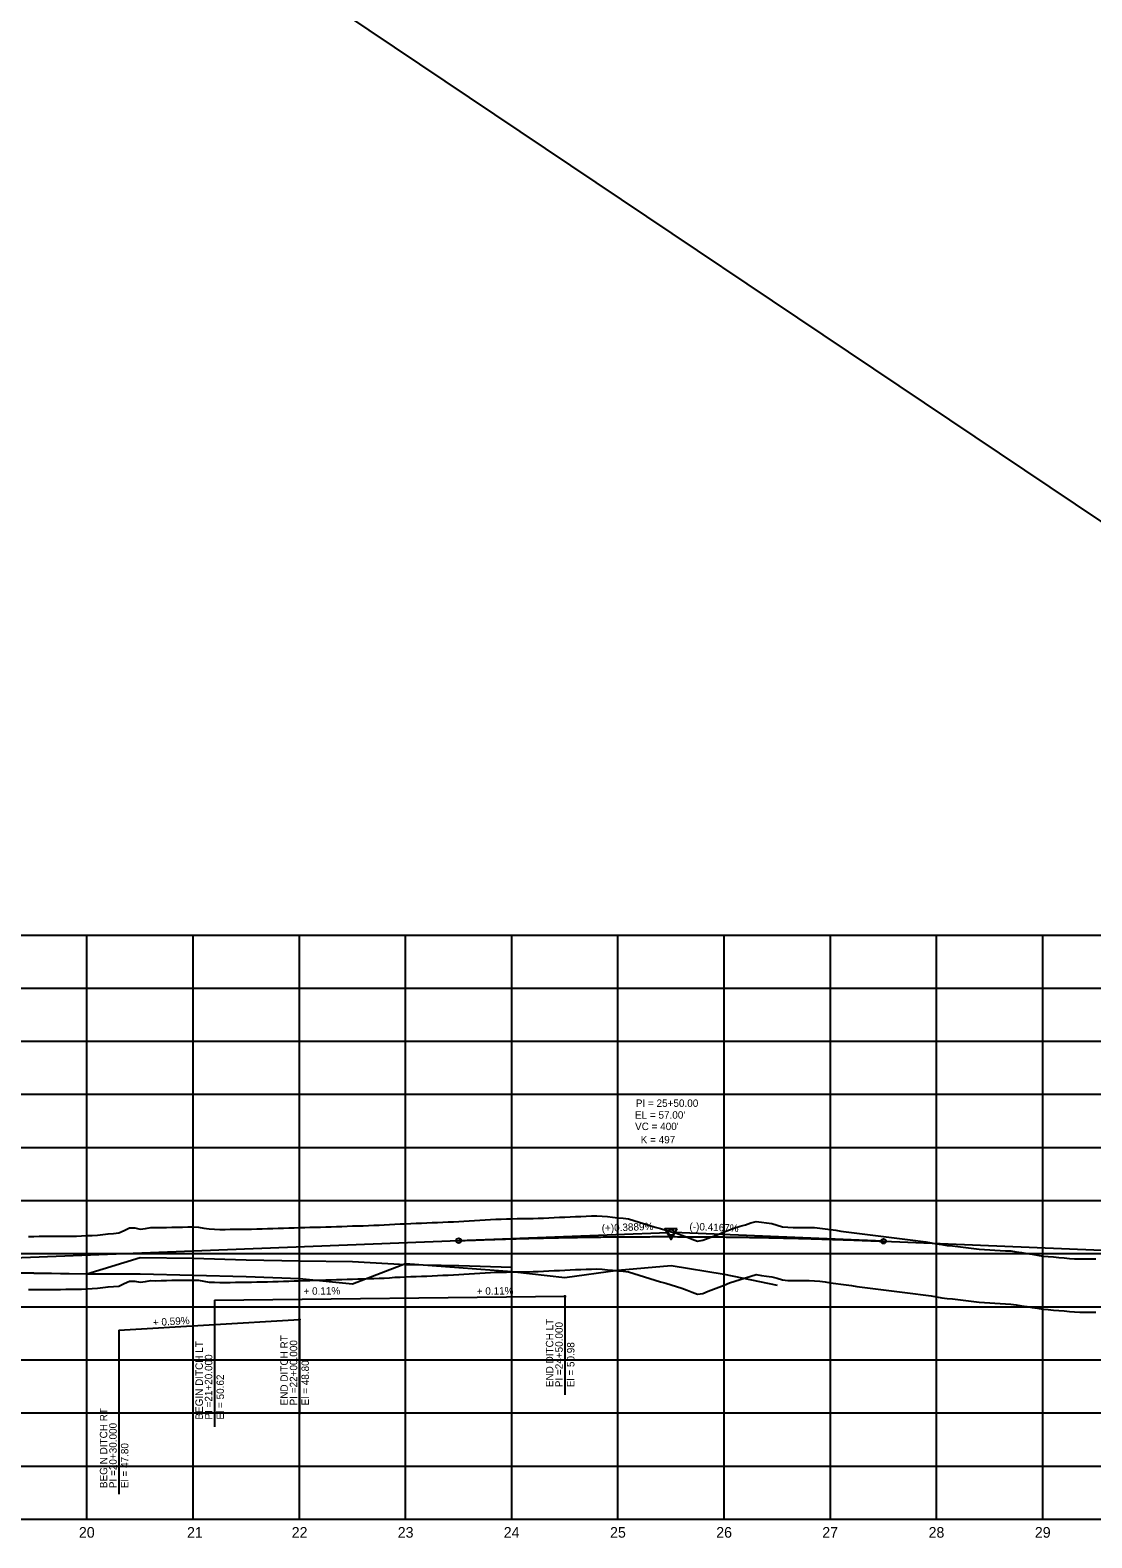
# Model space of a CAD drawing. Extents: x 2345490 to 2445302, y 465165 to 573888.
# Drawn here: x 2382268 to 2383268, y 557766 to 559186 of the extents above; entities that cross this region are included whole.
import ezdxf

# ---------------------------------------------------------------- set-up
doc = ezdxf.new("R2010")
doc.units = 0
for name, color, linetype in [('Old_Level_1', 7, 'Continuous'), ('Old_Level_2', 7, 'Continuous'), ('Old_Level_3', 7, 'Continuous'), ('Old_Level_57', 7, 'Continuous'), ('Old_Level_62', 7, 'Continuous'), ('Old_Level_63', 7, 'Continuous')]:
    doc.layers.add(name, color=color, linetype=linetype)

msp = doc.modelspace()

# ---------------------------------------------------------------- linework, layer by layer
at = {"layer": 'Old_Level_1'}
for points in [[(2382321.5425, 558001.0325), (2382326.5425, 558001.31675), (2382331.5425, 558001.601), (2382336.5425, 558002.057), (2382341.5425, 558002.719), (2382346.5425, 558003.0015), (2382351.5425, 558003.5645), (2382356.5425, 558005.94325), (2382361.5425, 558008.322), (2382366.5425, 558008.2755), (2382371.5425, 558007.1595), (2382376.5425, 558007.7375), (2382381.5425, 558008.74525), (2382386.5425, 558008.6005), (2382391.5425, 558008.702), (2382396.5425, 558008.8405), (2382401.5425, 558008.979), (2382406.5425, 558009.118), (2382411.5425, 558009.16725), (2382416.5425, 558009.1965), (2382421.5425, 558009.226), (2382426.5425, 558008.95975), (2382431.5425, 558008.044), (2382436.5425, 558007.33925), (2382441.5425, 558007.21075), (2382446.5425, 558006.789), (2382451.5425, 558006.89375), (2382456.5425, 558006.99), (2382461.5425, 558007.08675), (2382466.5425, 558007.18425), (2382471.5425, 558007.23), (2382476.5425, 558007.24775), (2382481.5425, 558007.39325), (2382486.5425, 558007.54), (2382491.5425, 558007.68775), (2382496.5425, 558007.837), (2382501.5425, 558007.97575), (2382506.5425, 558008.1255), (2382511.5425, 558008.2765), (2382516.5425, 558008.42875), (2382521.5425, 558008.58225), (2382526.5425, 558008.737), (2382531.5425, 558008.862), (2382536.5425, 558009.00875), (2382541.5425, 558009.15675), (2382546.5425, 558009.31125), (2382551.5425, 558009.46975), (2382556.5425, 558009.62975), (2382561.5425, 558009.7915), (2382566.5425, 558009.95825), (2382571.5425, 558010.1115), (2382576.5425, 558010.2665), (2382581.5425, 558010.42325), (2382586.5425, 558010.59125), (2382591.5425, 558010.77925), (2382596.5425, 558010.93275), (2382601.5425, 558011.11825), (2382606.5425, 558011.442), (2382611.5425, 558011.815), (2382616.5425, 558012.083), (2382621.5425, 558012.2665), (2382626.5425, 558012.45225), (2382631.5425, 558012.64025), (2382636.5425, 558012.831), (2382641.5425, 558013.024), (2382646.5425, 558013.269), (2382651.5425, 558013.5195), (2382656.5425, 558013.73375), (2382661.5425, 558013.951), (2382666.5425, 558014.17075), (2382671.5425, 558014.4275), (2382676.5425, 558014.7165), (2382681.5425, 558015.00875), (2382686.5425, 558015.304), (2382691.5425, 558015.597), (2382696.5425, 558015.8945), (2382701.5425, 558016.20425), (2382706.5425, 558016.495), (2382711.5425, 558016.6295), (2382716.5425, 558016.7655), (2382721.5425, 558016.9035), (2382726.5425, 558017.04025), (2382731.5425, 558017.0705), (2382736.5425, 558017.10275), (2382741.5425, 558017.137), (2382746.5425, 558017.3595), (2382751.5425, 558017.6255), (2382756.5425, 558017.89375), (2382761.5425, 558018.151), (2382766.5425, 558018.2795), (2382771.5425, 558018.508), (2382776.5425, 558018.797), (2382781.5425, 558019.047), (2382786.5425, 558019.18725), (2382791.5425, 558019.3475), (2382796.5425, 558019.56325), (2382801.5425, 558019.78075), (2382806.5425, 558019.49125), (2382811.5425, 558018.90925), (2382816.5425, 558018.435), (2382821.5425, 558017.95625)], [(2382821.5425, 558017.95625), (2382826.5425, 558017.4735), (2382831.5425, 558016.962), (2382836.5425, 558015.4025), (2382841.5425, 558013.82975), (2382846.5425, 558012.24475), (2382851.5425, 558010.648), (2382856.5425, 558009.05625), (2382861.5425, 558007.6185), (2382866.5425, 558006.16875), (2382871.5425, 558004.6825), (2382876.5425, 558003.22575), (2382881.5425, 558001.498), (2382886.5425, 557999.6715), (2382891.5425, 557997.73575), (2382896.5425, 557995.78775), (2382901.5425, 557996.65625), (2382906.5425, 557998.6755), (2382911.5425, 558000.5625), (2382916.5425, 558002.50375), (2382921.5425, 558004.4935), (2382926.5425, 558006.4955), (2382931.5425, 558008.26475), (2382936.5425, 558009.80975), (2382941.5425, 558011.36625), (2382946.5425, 558012.97575), (2382951.5425, 558014.2955), (2382956.5425, 558013.65175), (2382961.5425, 558013.00675), (2382966.5425, 558012.36025), (2382971.5425, 558011.014), (2382976.5425, 558009.30475), (2382981.5425, 558008.8615), (2382986.5425, 558008.81725), (2382991.5425, 558008.7735), (2382996.5425, 558008.73), (2383001.5425, 558008.687), (2383006.5425, 558008.556), (2383011.5425, 558008.08625), (2383016.5425, 558007.40225), (2383021.5425, 558006.71775), (2383026.5425, 558006.03275), (2383031.5425, 558005.3475), (2383036.5425, 558004.662), (2383041.5425, 558003.976), (2383046.5425, 558003.28975), (2383051.5425, 558002.60325), (2383056.5425, 558001.9795), (2383061.5425, 558001.35625), (2383066.5425, 558000.73225), (2383071.5425, 558000.10825), (2383076.5425, 557999.48375), (2383081.5425, 557998.85875), (2383086.5425, 557998.23325), (2383091.5425, 557997.60775), (2383096.5425, 557996.99325), (2383101.5425, 557996.38225), (2383106.5425, 557995.71975), (2383111.5425, 557995.05675), (2383116.5425, 557994.2925), (2383121.5425, 557993.4425), (2383126.5425, 557992.59125), (2383131.5425, 557991.808), (2383136.5425, 557991.47225), (2383141.5425, 557990.9185), (2383146.5425, 557990.26625), (2383151.5425, 557989.61325), (2383156.5425, 557988.95975), (2383161.5425, 557988.32225), (2383166.5425, 557988.0065), (2383171.5425, 557987.6905), (2383176.5425, 557987.374), (2383181.5425, 557987.05725), (2383186.5425, 557986.837), (2383191.5425, 557986.621), (2383196.5425, 557985.8325), (2383201.5425, 557985.037), (2383206.5425, 557984.24075), (2383211.5425, 557983.44375), (2383216.5425, 557982.5975), (2383221.5425, 557981.72625), (2383226.5425, 557981.48025), (2383231.5425, 557981.018), (2383236.5425, 557980.5555), (2383241.5425, 557980.09275), (2383246.5425, 557979.6295), (2383251.5425, 557979.16575), (2383256.5425, 557979.13225), (2383261.5425, 557979.1255), (2383266.5425, 557979.11825), (2383271.5425, 557979.06925)], [(2382266.5425, 558000.263), (2382271.5425, 558000.3275), (2382276.5425, 558000.392), (2382281.5425, 558000.4565), (2382286.5425, 558000.454), (2382291.5425, 558000.388), (2382296.5425, 558000.41875), (2382301.5425, 558000.49725), (2382306.5425, 558000.55625), (2382311.5425, 558000.50225), (2382316.5425, 558000.74825), (2382321.5425, 558001.0325)]]:
    msp.add_lwpolyline(points, dxfattribs=at)
at = {"layer": 'Old_Level_2'}
for p, q in [((2381971.5425, 558019.113), (2382671.5425, 558046.335)), ((2382671.5425, 558046.335), (2382868.79475, 558054.006)), ((2383071.5425, 558045.7795), (2382874.29025, 558053.9985)), ((2383071.5425, 558045.7795), (2383361.5425, 558033.69625))]:
    msp.add_line(p, q, dxfattribs=at)
msp.add_lwpolyline([(2382877.43325, 558057.51575), (2382865.69075, 558057.50125), (2382871.57425, 558047.383)], close=True, dxfattribs=at)
for centre, radius in [((2382871.5425, 558054.113), 2.75), ((2382671.5425, 558046.335), 2.25), ((2383071.5425, 558045.7795), 2.25)]:
    msp.add_circle(centre, radius, dxfattribs=at)
msp.add_spline([(2382671.5425, 558046.335), (2382679.5425, 558046.63975), (2382687.5425, 558046.9315), (2382695.5425, 558047.2105), (2382703.5425, 558047.4765), (2382711.5425, 558047.7295), (2382719.5425, 558047.96975), (2382727.5425, 558048.197), (2382735.5425, 558048.4115), (2382743.5425, 558048.613), (2382751.5425, 558048.80175), (2382759.5425, 558048.9775), (2382767.5425, 558049.1405), (2382775.5425, 558049.2905), (2382783.5425, 558049.4275), (2382791.5425, 558049.55175), (2382799.5425, 558049.663), (2382807.5425, 558049.7615), (2382815.5425, 558049.847), (2382823.5425, 558049.91975), (2382831.5425, 558049.9795), (2382839.5425, 558050.0265), (2382847.5425, 558050.0605), (2382855.5425, 558050.0815), (2382863.5425, 558050.08975), (2382871.5425, 558050.085), (2382879.5425, 558050.0675), (2382887.5425, 558050.037), (2382895.5425, 558049.99375), (2382903.5425, 558049.9375), (2382911.5425, 558049.8685), (2382919.5425, 558049.7865), (2382927.5425, 558049.6915), (2382935.5425, 558049.58375), (2382943.5425, 558049.463), (2382951.5425, 558049.3295), (2382959.5425, 558049.183), (2382967.5425, 558049.02375), (2382975.5425, 558048.8515), (2382983.5425, 558048.6665), (2382991.5425, 558048.4685), (2382999.5425, 558048.2575), (2383007.5425, 558048.03375), (2383015.5425, 558047.797), (2383023.5425, 558047.5475), (2383031.5425, 558047.285), (2383039.5425, 558047.00975), (2383047.5425, 558046.7215), (2383055.5425, 558046.4205), (2383063.5425, 558046.1065), (2383071.5425, 558045.7795)], degree=3, dxfattribs=at)
at = {"layer": 'Old_Level_3'}
for p, q in [((2382441.5425, 557990.313), (2382771.5425, 557993.913)), ((2382441.5425, 557990.313), (2382441.5425, 557871.06918)), ((2382771.5425, 557993.913), (2382771.5425, 557901.14511)), ((2382351.5425, 557962.113), (2382521.5425, 557972.113)), ((2382521.5425, 557972.113), (2382521.5425, 557882.91727)), ((2382351.5425, 557962.113), (2382351.5425, 557807.72745))]:
    msp.add_line(p, q, dxfattribs=at)
for centre in [(2382771.5425, 557993.913), (2382521.5425, 557972.113)]:
    msp.add_circle(centre, 0.5, dxfattribs=at)
at = {"layer": 'Old_Level_57'}
for p, q in [((2381271.54275, 558334.11325), (2393041.55275, 558334.11325)), ((2382321.54225, 557784.21325), (2382321.54225, 558334.21325)), ((2382321.54225, 557784.11325), (2382321.54225, 558334.11325)), ((2382421.54225, 557784.21325), (2382421.54225, 558334.21325)), ((2382421.54225, 557784.11325), (2382421.54225, 558334.11325)), ((2382521.54225, 557784.21325), (2382521.54225, 558334.21325)), ((2382521.54225, 557784.11325), (2382521.54225, 558334.11325)), ((2382621.54225, 557784.21325), (2382621.54225, 558334.21325)), ((2382621.54225, 557784.11325), (2382621.54225, 558334.11325)), ((2382721.54225, 557784.21325), (2382721.54225, 558334.21325)), ((2382721.54225, 557784.11325), (2382721.54225, 558334.11325)), ((2382821.54225, 557784.21325), (2382821.54225, 558334.21325)), ((2382821.54225, 557784.11325), (2382821.54225, 558334.11325)), ((2382921.54225, 557784.21325), (2382921.54225, 558334.21325)), ((2382921.54225, 557784.11325), (2382921.54225, 558334.11325)), ((2383021.54225, 557784.21325), (2383021.54225, 558334.21325)), ((2383021.54225, 557784.11325), (2383021.54225, 558334.11325)), ((2383121.54225, 557784.21325), (2383121.54225, 558334.21325)), ((2383121.54225, 557784.11325), (2383121.54225, 558334.11325)), ((2383221.54225, 557784.21325), (2383221.54225, 558334.21325)), ((2383221.54225, 557784.11325), (2383221.54225, 558334.11325)), ((2381271.54275, 558284.11325), (2393041.55275, 558284.11325)), ((2381271.54275, 558234.11325), (2393041.55275, 558234.11325)), ((2381271.54275, 558184.11325), (2393041.55275, 558184.11325)), ((2381271.54275, 558134.11325), (2393041.55275, 558134.11325)), ((2381271.54275, 558084.11325), (2393041.55275, 558084.11325)), ((2381271.5425, 558034.11325), (2393041.55275, 558034.11325)), ((2381271.54275, 557984.11325), (2393041.55275, 557984.11325)), ((2381271.5425, 557934.11325), (2393041.55275, 557934.11325)), ((2381271.54275, 557884.11325), (2393041.55275, 557884.11325)), ((2381271.5425, 557834.11325), (2393041.55275, 557834.11325)), ((2381271.54275, 557784.11325), (2393041.55275, 557784.11325))]:
    msp.add_line(p, q, dxfattribs=at)
at = {"layer": 'Old_Level_62'}
msp.add_line((2383701.45891, 558438.22314), (2372247.98083, 566129.10196), dxfattribs=at)
for points in [[(2382321.5425, 558051.0385), (2382326.5425, 558051.32275), (2382331.5425, 558051.607), (2382336.5425, 558052.063), (2382341.5425, 558052.725), (2382346.5425, 558053.0075), (2382351.5425, 558053.5705), (2382356.5425, 558055.94925), (2382361.5425, 558058.328), (2382366.5425, 558058.2815), (2382371.5425, 558057.1655), (2382376.5425, 558057.7435), (2382381.5425, 558058.75125), (2382386.5425, 558058.6065), (2382391.5425, 558058.708), (2382396.5425, 558058.8465), (2382401.5425, 558058.985), (2382406.5425, 558059.124), (2382411.5425, 558059.17325), (2382416.5425, 558059.2025), (2382421.5425, 558059.232), (2382426.5425, 558058.96575), (2382431.5425, 558058.05), (2382436.5425, 558057.34525), (2382441.5425, 558057.21675), (2382446.5425, 558056.795), (2382451.5425, 558056.89975), (2382456.5425, 558056.996), (2382461.5425, 558057.09275), (2382466.5425, 558057.19025), (2382471.5425, 558057.236), (2382476.5425, 558057.25375), (2382481.5425, 558057.39925), (2382486.5425, 558057.546), (2382491.5425, 558057.69375), (2382496.5425, 558057.843), (2382501.5425, 558057.98175), (2382506.5425, 558058.1315), (2382511.5425, 558058.2825), (2382516.5425, 558058.43475), (2382521.5425, 558058.58825), (2382526.5425, 558058.743), (2382531.5425, 558058.868), (2382536.5425, 558059.01475), (2382541.5425, 558059.16275), (2382546.5425, 558059.31725), (2382551.5425, 558059.47575), (2382556.5425, 558059.63575), (2382561.5425, 558059.7975), (2382566.5425, 558059.96425), (2382571.5425, 558060.1175), (2382576.5425, 558060.2725), (2382581.5425, 558060.42925), (2382586.5425, 558060.59725), (2382591.5425, 558060.78525), (2382596.5425, 558060.93875), (2382601.5425, 558061.12425), (2382606.5425, 558061.448), (2382611.5425, 558061.821), (2382616.5425, 558062.089), (2382621.5425, 558062.2725), (2382626.5425, 558062.45825), (2382631.5425, 558062.64625), (2382636.5425, 558062.837), (2382641.5425, 558063.03), (2382646.5425, 558063.275), (2382651.5425, 558063.5255), (2382656.5425, 558063.73975), (2382661.5425, 558063.957), (2382666.5425, 558064.17675), (2382671.5425, 558064.4335), (2382676.5425, 558064.7225), (2382681.5425, 558065.01475), (2382686.5425, 558065.31), (2382691.5425, 558065.603), (2382696.5425, 558065.9005), (2382701.5425, 558066.21025), (2382706.5425, 558066.501), (2382711.5425, 558066.6355), (2382716.5425, 558066.7715), (2382721.5425, 558066.9095), (2382726.5425, 558067.04625), (2382731.5425, 558067.0765), (2382736.5425, 558067.10875), (2382741.5425, 558067.143), (2382746.5425, 558067.3655), (2382751.5425, 558067.6315), (2382756.5425, 558067.89975), (2382761.5425, 558068.157), (2382766.5425, 558068.2855), (2382771.5425, 558068.514), (2382776.5425, 558068.803), (2382781.5425, 558069.053), (2382786.5425, 558069.19325), (2382791.5425, 558069.3535), (2382796.5425, 558069.56925), (2382801.5425, 558069.78675), (2382806.5425, 558069.49725), (2382811.5425, 558068.91525), (2382816.5425, 558068.441), (2382821.5425, 558067.96225)], [(2382821.5425, 558067.96225), (2382826.5425, 558067.4795), (2382831.5425, 558066.968), (2382836.5425, 558065.4085), (2382841.5425, 558063.83575), (2382846.5425, 558062.25075), (2382851.5425, 558060.654), (2382856.5425, 558059.06225), (2382861.5425, 558057.6245), (2382866.5425, 558056.17475), (2382871.5425, 558054.6885), (2382876.5425, 558053.23175), (2382881.5425, 558051.504), (2382886.5425, 558049.6775), (2382891.5425, 558047.74175), (2382896.5425, 558045.79375), (2382901.5425, 558046.66225), (2382906.5425, 558048.6815), (2382911.5425, 558050.5685), (2382916.5425, 558052.50975), (2382921.5425, 558054.4995), (2382926.5425, 558056.5015), (2382931.5425, 558058.27075), (2382936.5425, 558059.81575), (2382941.5425, 558061.37225), (2382946.5425, 558062.98175), (2382951.5425, 558064.3015), (2382956.5425, 558063.65775), (2382961.5425, 558063.01275), (2382966.5425, 558062.36625), (2382971.5425, 558061.02), (2382976.5425, 558059.31075), (2382981.5425, 558058.8675), (2382986.5425, 558058.82325), (2382991.5425, 558058.7795), (2382996.5425, 558058.736), (2383001.5425, 558058.693), (2383006.5425, 558058.562), (2383011.5425, 558058.09225), (2383016.5425, 558057.40825), (2383021.5425, 558056.72375), (2383026.5425, 558056.03875), (2383031.5425, 558055.3535), (2383036.5425, 558054.668), (2383041.5425, 558053.982), (2383046.5425, 558053.29575), (2383051.5425, 558052.60925), (2383056.5425, 558051.9855), (2383061.5425, 558051.36225), (2383066.5425, 558050.73825), (2383071.5425, 558050.11425), (2383076.5425, 558049.48975), (2383081.5425, 558048.86475), (2383086.5425, 558048.23925), (2383091.5425, 558047.61375), (2383096.5425, 558046.99925), (2383101.5425, 558046.38825), (2383106.5425, 558045.72575), (2383111.5425, 558045.06275), (2383116.5425, 558044.2985), (2383121.5425, 558043.4485), (2383126.5425, 558042.59725), (2383131.5425, 558041.814), (2383136.5425, 558041.47825), (2383141.5425, 558040.9245), (2383146.5425, 558040.27225), (2383151.5425, 558039.61925), (2383156.5425, 558038.96575), (2383161.5425, 558038.32825), (2383166.5425, 558038.0125), (2383171.5425, 558037.6965), (2383176.5425, 558037.38), (2383181.5425, 558037.06325), (2383186.5425, 558036.843), (2383191.5425, 558036.627), (2383196.5425, 558035.8385), (2383201.5425, 558035.043), (2383206.5425, 558034.24675), (2383211.5425, 558033.44975), (2383216.5425, 558032.6035), (2383221.5425, 558031.73225), (2383226.5425, 558031.48625), (2383231.5425, 558031.024), (2383236.5425, 558030.5615), (2383241.5425, 558030.09875), (2383246.5425, 558029.6355), (2383251.5425, 558029.17175), (2383256.5425, 558029.13825), (2383261.5425, 558029.1315), (2383266.5425, 558029.12425), (2383271.5425, 558029.07525)], [(2382266.5425, 558050.269), (2382271.5425, 558050.3335), (2382276.5425, 558050.398), (2382281.5425, 558050.4625), (2382286.5425, 558050.46), (2382291.5425, 558050.394), (2382296.5425, 558050.42475), (2382301.5425, 558050.50325), (2382306.5425, 558050.56225), (2382311.5425, 558050.50825), (2382316.5425, 558050.75425), (2382321.5425, 558051.0385)], [(2381921.5425, 558014.613), (2381971.5425, 558017.013), (2382021.5425, 558016.713), (2382071.5425, 558015.713), (2382121.5425, 558015.613), (2382171.5425, 558016.013), (2382221.5425, 558016.113), (2382271.5425, 558015.713), (2382321.5425, 558015.213), (2382371.5425, 558030.313), (2382421.5425, 558029.713), (2382471.5425, 558028.413), (2382521.5425, 558027.213), (2382571.5425, 558026.613), (2382621.5425, 558023.713), (2382671.5425, 558023.013), (2382721.5425, 558021.313)], [(2381921.5425, 558018.913), (2381971.5425, 558019.113), (2382021.5425, 558018.313), (2382071.5425, 558017.413), (2382121.5425, 558016.713), (2382171.5425, 558016.113), (2382221.5425, 558016.013), (2382271.5425, 558016.013), (2382321.5425, 558015.213), (2382371.5425, 558015.013), (2382421.5425, 558013.913), (2382471.5425, 558012.513), (2382521.5425, 558010.713), (2382571.5425, 558005.613), (2382621.5425, 558024.813), (2382671.5425, 558021.113), (2382721.5425, 558017.413), (2382771.5425, 558011.613), (2382821.5425, 558018.413), (2382871.5425, 558022.913), (2382921.5425, 558014.613), (2382971.5425, 558004.513)]]:
    msp.add_lwpolyline(points, dxfattribs=at)
at = {"layer": 'Old_Level_63'}
msp.add_line((2381321.5425, 557784.113), (2393019.104, 557784.113), dxfattribs=at)

# ---------------------------------------------------------------- texts
at = {"layer": 'Old_Level_1'}
for s, p in [('20', (2382313.929, 557766.613)), ('21', (2382415.7685, 557766.613)), ('22', (2382514.31675, 557766.613)), ('23', (2382614.1515, 557766.613)), ('24', (2382713.994, 557766.613)), ('25', (2382814.0865, 557766.613)), ('26', (2382914.0275, 557766.613)), ('27', (2383013.885, 557766.613)), ('28', (2383114.01075, 557766.613)), ('29', (2383214.053, 557766.613))]:
    msp.add_text(s, height=10.000001, dxfattribs=at).set_placement(p)
at = {"layer": 'Old_Level_2'}
for s, height, p in [('PI = 25+50.00', 7.0000005, (2382838.36025, 558172.265)), ("VC = 400'", 7.000001, (2382837.61575, 558150.4255)), ("EL = 57.00'", 7.0000005, (2382837.56225, 558161.19325)), ('K = 497', 7.000001, (2382842.9395, 558137.92075))]:
    msp.add_text(s, height=height, dxfattribs=at).set_placement(p)
for s, rotation, p in [('(+)0.3889%', 2.22704722, (2382806.34625, 558054.5795)), ('(-)0.4167%', 357.61405556, (2382888.72775, 558056.3995))]:
    msp.add_text(s, height=7.000001, rotation=rotation, dxfattribs=at).set_placement(p)
at = {"layer": 'Old_Level_3'}
for s, height, rotation, p in [('+ 0.11%', 7.000001, 0.62501944, (2382525.45594, 557995.30727)), ('+ 0.11%', 7.000001, 0.62501944, (2382688.59506, 557995.30727)), ('+ 0.59%', 7.000001, 3.36646111, (2382383.80539, 557965.7638)), ('END DITCH LT', 7.0000005, 90, (2382760.6686, 557908.31478)), ('END DITCH RT', 7.0000005, 90, (2382510.6686, 557891.19489)), ('PI =24+50.000', 7.0000005, 90, (2382769.5425, 557908.31478)), ('BEGIN DITCH LT', 7.0000005, 90, (2382430.6686, 557877.82872)), ('PI =22+00.000', 7.0000005, 90, (2382519.5425, 557891.19489)), ('El = 50.98', 7.000001, 90, (2382780.5425, 557908.31478)), ('PI =21+20.000', 7.0000005, 90, (2382439.5425, 557877.82872)), ('El = 48.80', 7.000001, 90, (2382530.5425, 557891.19489)), ('El = 50.62', 7.000001, 90, (2382450.5425, 557877.82872)), ('BEGIN DITCH RT', 7.0000005, 90, (2382340.6686, 557813.29621)), ('PI =20+30.000', 7.0000005, 90, (2382349.5425, 557813.29621)), ('El = 47.80', 7.000001, 90, (2382360.5425, 557813.29621))]:
    msp.add_text(s, height=height, rotation=rotation, dxfattribs=at).set_placement(p)

doc.saveas('drawing.dxf')
